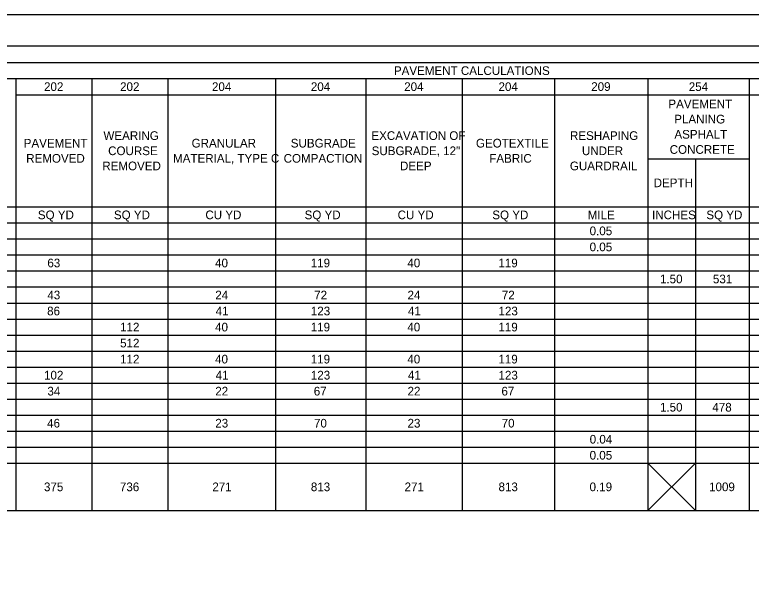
# Model space of a CAD drawing. Extents: x -27.3 to 69.3, y 0 to 30.
# Drawn here: x 8.54 to 20.43, y 12.94 to 22 of the extents above; entities that cross this region are included whole.
import ezdxf

# ---------------------------------------------------------------- set-up
doc = ezdxf.new("R2010")
doc.units = 0
for name, color, linetype in [('Default', 7, 'Continuous'), ('SH_Border', 7, 'Continuous'), ('SH_Cut_Line', 7, 'Continuous')]:
    doc.layers.add(name, color=color, linetype=linetype)

msp = doc.modelspace()

# ---------------------------------------------------------------- linework, layer by layer
at = {"layer": 'Default'}
for p, q in [((1.762, 21.228), (29.869, 21.228)), ((1.762, 20.969), (29.869, 20.969)), ((8.56, 20.969), (8.56, 14.003)), ((9.788, 20.969), (9.788, 14.003)), ((11.016, 20.969), (11.016, 14.003)), ((12.753, 20.969), (12.753, 14.003)), ((14.21, 20.969), (14.21, 14.003)), ((15.767, 20.969), (15.767, 14.003)), ((17.257, 20.969), (17.257, 14.003)), ((18.764, 20.969), (18.764, 14.003)), ((20.402, 20.969), (20.402, 14.003)), ((8.56, 20.71), (26.692, 20.71)), ((18.764, 19.676), (20.402, 19.676)), ((19.534, 19.676), (19.534, 14.003)), ((3.416, 18.9), (26.692, 18.9)), ((1.762, 18.642), (29.869, 18.642)), ((1.762, 18.383), (26.692, 18.383)), ((1.762, 18.125), (29.869, 18.125)), ((1.762, 17.866), (29.869, 17.866)), ((1.762, 17.608), (29.869, 17.608)), ((1.762, 17.349), (29.869, 17.349)), ((1.762, 17.09), (29.869, 17.09)), ((1.762, 16.832), (29.869, 16.832)), ((1.762, 16.573), (29.869, 16.573)), ((1.762, 16.315), (29.869, 16.315)), ((1.762, 16.056), (29.869, 16.056)), ((1.762, 15.798), (29.869, 15.798)), ((1.762, 15.539), (29.869, 15.539)), ((1.762, 15.28), (29.869, 15.28)), ((1.762, 15.022), (26.692, 15.022)), ((1.762, 14.763), (26.692, 14.763)), ((18.764, 14.003), (19.534, 14.763)), ((18.764, 14.763), (19.534, 14.003)), ((1.762, 14.003), (29.869, 14.003))]:
    msp.add_line(p, q, dxfattribs=at)
at = {"layer": 'SH_Border'}
msp.add_lwpolyline([(1.5, 21.5), (33.5, 21.5), (33.5, 0.5), (1.5, 0.5)], close=True, dxfattribs=at)
at = {"layer": 'SH_Cut_Line'}
msp.add_lwpolyline([(0, 0), (34, 0), (34, 22), (0, 22)], close=True, dxfattribs=at)

# ---------------------------------------------------------------- texts
at = {"layer": 'Default'}
for s, height, p in [('PAVEMENT CALCULATIONS', 0.13993, (14.664, 21.028)), ('202', 0.1399, (9.015, 20.77)), ('202', 0.1399, (10.243, 20.77)), ('204', 0.1399, (11.726, 20.77)), ('204', 0.1399, (13.323, 20.77)), ('204', 0.1399, (14.83, 20.77)), ('204', 0.1399, (16.353, 20.77)), ('209', 0.1399, (17.85, 20.771)), ('254', 0.1399, (19.425, 20.77)), ('PAVEMENT ', 0.1399, (19.096, 20.491)), ('PLANING ', 0.1399, (19.19, 20.246)), ('WEARING ', 0.1399, (9.974, 19.98)), ('EXCAVATION OF ', 0.13993, (14.301, 19.98)), ('RESHAPING ', 0.1399, (17.507, 19.98)), ('ASPHALT ', 0.1399, (19.193, 20.001)), ('PAVEMENT ', 0.1399, (8.687, 19.858)), ('GRANULAR ', 0.1399, (11.398, 19.858)), ('SUBGRADE ', 0.1399, (12.999, 19.858)), ('GEOTEXTILE ', 0.13993, (15.989, 19.858)), ('COURSE ', 0.1399, (10.05, 19.735)), ('SUBGRADE, 12" ', 0.13993, (14.305, 19.735)), ('UNDER ', 0.1399, (17.7, 19.735)), ('CONCRETE', 0.1399, (19.117, 19.756)), ('REMOVED', 0.1399, (8.727, 19.613)), ('MATERIAL, TYPE C', 0.13993, (11.098, 19.613)), ('COMPACTION', 0.1399, (12.884, 19.613)), ('FABRIC', 0.1399, (16.204, 19.613)), ('REMOVED', 0.1399, (9.956, 19.491)), ('DEEP', 0.1399, (14.763, 19.491)), ('GUARDRAIL', 0.1399, (17.505, 19.491)), ('DEPTH', 0.1399, (18.858, 19.218)), ('SQ YD', 0.1399, (8.915, 18.701)), ('SQ YD', 0.1399, (10.143, 18.701)), ('CU YD', 0.1399, (11.62, 18.701)), ('SQ YD', 0.1399, (13.222, 18.701)), ('CU YD', 0.1399, (14.724, 18.701)), ('SQ YD', 0.1399, (16.253, 18.701)), ('MILE', 0.1399, (17.793, 18.701)), ('INCHES', 0.1399, (18.832, 18.701)), ('SQ YD', 0.1399, (19.709, 18.701)), ('0.05', 0.1399, (17.824, 18.443)), ('0.05', 0.1399, (17.824, 18.184)), ('63', 0.1399, (9.069, 17.925)), ('40', 0.1399, (11.777, 17.925)), ('119', 0.1399, (13.321, 17.925)), ('40', 0.1399, (14.881, 17.925)), ('119', 0.1399, (16.351, 17.925)), ('1.50', 0.1399, (18.96, 17.667)), ('531', 0.1399, (19.815, 17.667)), ('43', 0.1399, (9.069, 17.408)), ('24', 0.1399, (11.78, 17.408)), ('72', 0.1399, (13.377, 17.408)), ('24', 0.1399, (14.884, 17.408)), ('72', 0.1399, (16.407, 17.408)), ('86', 0.1399, (9.065, 17.15)), ('41', 0.1399, (11.786, 17.15)), ('123', 0.1399, (13.323, 17.15)), ('41', 0.1399, (14.89, 17.15)), ('123', 0.1399, (16.353, 17.15)), ('112', 0.1399, (10.243, 16.891)), ('40', 0.1399, (11.777, 16.891)), ('119', 0.1399, (13.321, 16.891)), ('40', 0.1399, (14.881, 16.891)), ('119', 0.1399, (16.351, 16.891)), ('512', 0.1399, (10.243, 16.633)), ('112', 0.1399, (10.243, 16.374)), ('40', 0.1399, (11.777, 16.374)), ('119', 0.1399, (13.321, 16.374)), ('40', 0.1399, (14.881, 16.374)), ('119', 0.1399, (16.351, 16.374)), ('102', 0.1399, (9.015, 16.115)), ('41', 0.1399, (11.786, 16.115)), ('123', 0.1399, (13.323, 16.115)), ('41', 0.1399, (14.89, 16.115)), ('123', 0.1399, (16.353, 16.115)), ('34', 0.1399, (9.069, 15.857)), ('22', 0.1399, (11.78, 15.857)), ('67', 0.1399, (13.37, 15.857)), ('22', 0.1399, (14.884, 15.857)), ('67', 0.1399, (16.4, 15.857)), ('1.50', 0.1399, (18.96, 15.598)), ('478', 0.1399, (19.806, 15.598)), ('46', 0.1399, (9.065, 15.34)), ('23', 0.1399, (11.78, 15.34)), ('70', 0.1399, (13.374, 15.34)), ('23', 0.1399, (14.884, 15.34)), ('70', 0.1399, (16.404, 15.34)), ('0.04', 0.1399, (17.825, 15.081)), ('0.05', 0.1399, (17.824, 14.823)), ('375', 0.1399, (9.014, 14.313)), ('736', 0.1399, (10.24, 14.313)), ('271', 0.1399, (11.732, 14.313)), ('813', 0.1399, (13.323, 14.313)), ('271', 0.1399, (14.836, 14.313)), ('813', 0.1399, (16.353, 14.313)), ('0.19', 0.1399, (17.823, 14.313)), ('1009', 0.1399, (19.753, 14.313))]:
    msp.add_text(s, height=height, dxfattribs=at).set_placement(p)

doc.saveas('drawing.dxf')
